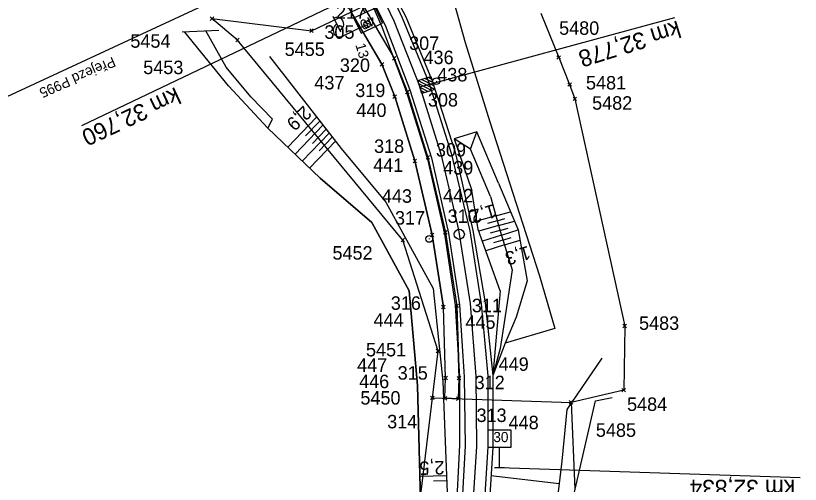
# Model space of a CAD drawing. Extents: x -804166 to -803706, y -1151030 to -1150147.
# Drawn here: x -803925.7 to -803809.4, y -1150585.6 to -1150516 of the extents above; entities that cross this region are included whole.
import ezdxf

# ---------------------------------------------------------------- set-up
doc = ezdxf.new("R2010")
doc.units = 0
for name, color, linetype in [('0381KM032-037P - Vrstva 1', 7, 'Continuous'), ('0381KM032-037P - Vrstva 16', 7, 'Continuous'), ('0381KM032-037P - Vrstva 17', 7, 'Continuous'), ('0381KM032-037P - Vrstva 25', 7, 'Continuous'), ('0381KM032-037P - Vrstva 27', 7, 'Continuous'), ('0381KM032-037P - Vrstva 3', 7, 'Continuous'), ('0381KM032-037P - Vrstva 4', 7, 'Continuous'), ('0381KM032-037P - Vrstva 48', 7, 'Continuous'), ('0381KM032-037P - Vrstva 49', 7, 'Continuous'), ('0381KM032-037P - Vrstva 5', 7, 'Continuous'), ('0381KM032-037P - Vrstva 50', 7, 'Continuous'), ('0381KM032-037P - Vrstva 55', 7, 'Continuous'), ('0381KM032-037P - Vrstva 7', 7, 'Continuous'), ('DZ - DZ_číslo', 7, 'Continuous'), ('DZ_CD - CD', 7, 'Continuous'), ('DZ_CD - CD_krizek', 7, 'Continuous'), ('DZ_CD - CD_čísla', 7, 'Continuous'), ('szdc - hran DP', 7, 'Continuous'), ('szdc - szdc_cislo', 7, 'Continuous'), ('szdc - szdc_krizek', 7, 'Continuous'), ('VB - VB', 7, 'Continuous'), ('VB - VB_cislo', 7, 'Continuous'), ('VB - VB_krizek', 7, 'Continuous')]:
    doc.layers.add(name, color=color, linetype=linetype)

msp = doc.modelspace()

# ---------------------------------------------------------------- linework, layer by layer
at = {"layer": '0381KM032-037P - Vrstva 1'}
for points in [[(-803874.07, -1150507.54), (-803869.67, -1150516.77), (-803865.8, -1150526.59), (-803862.65, -1150536.71)], [(-803862.65, -1150536.71), (-803860.06, -1150547.81), (-803858.36, -1150558.72), (-803857.51, -1150569.55), (-803857.43, -1150579.98), (-803858.1, -1150590.73), (-803859.58, -1150601.69), (-803861.73, -1150611.95), (-803864.69, -1150622.33), (-803868.31, -1150632.26), (-803873.12, -1150643.01), (-803878.78, -1150653.32), (-803884.46, -1150662.04), (-803890.68, -1150670.29), (-803894.47, -1150674.77)]]:
    msp.add_lwpolyline(points, dxfattribs=at)
at = {"layer": '0381KM032-037P - Vrstva 16'}
msp.add_line((-803901.04, -1150518.4), (-803895.63, -1150518.18), dxfattribs=at)
msp.add_lwpolyline([(-803888.33, -1150532.7), (-803887.64, -1150531.39), (-803890.89, -1150528.08), (-803894.53, -1150523.66), (-803897.53, -1150518.27)], dxfattribs=at)
at = {"layer": '0381KM032-037P - Vrstva 17'}
msp.add_lwpolyline([(-803867.91, -1150651.01), (-803864.19, -1150640.97), (-803863.34, -1150639.85), (-803860.11, -1150635.35), (-803857.38, -1150629.01), (-803845.63, -1150598.77), (-803839.77, -1150573.18), (-803837.29, -1150572.72)], dxfattribs=at)
at = {"layer": '0381KM032-037P - Vrstva 25'}
for p, q in [((-803877.52, -1150518.44), (-803878.68, -1150516.11)), ((-803873.28, -1150517.66), (-803874.12, -1150517.38)), ((-803873.13, -1150517.32), (-803874.04, -1150517.01)), ((-803874.08, -1150517.52), (-803877.21, -1150519.07))]:
    msp.add_line(p, q, dxfattribs=at)
msp.add_circle((-803873.63, -1150517.29), 0.5, dxfattribs=at)
msp.add_circle((-803873.63, -1150517.29), 0.5, dxfattribs=at)
for centre, start, end in [((-803878.09, -1150517.27), 295.6449, 117.05), ((-803877.66, -1150518.17), 116.3474, 296.3474)]:
    msp.add_arc(centre, 1, start, end, dxfattribs=at)
at = {"layer": '0381KM032-037P - Vrstva 27'}
msp.add_line((-803863.38, -1150525.68), (-803863.35, -1150525.78), dxfattribs=at)
msp.add_circle((-803863.37, -1150525.73), 0.5, dxfattribs=at)
at = {"layer": '0381KM032-037P - Vrstva 3'}
for p, q in [((-803865.8, -1150526.59), (-803827.99, -1150516.3)), ((-803863.75, -1150526.45), (-803865.59, -1150525.48)), ((-803863.91, -1150525.94), (-803865.09, -1150525.32)), ((-803864.07, -1150525.43), (-803864.58, -1150525.17)), ((-803863.59, -1150526.95), (-803866.1, -1150525.64)), ((-803864.1, -1150527.11), (-803865.94, -1150526.15)), ((-803864.61, -1150527.27), (-803865.78, -1150526.65)), ((-803865.11, -1150527.43), (-803865.62, -1150527.16))]:
    msp.add_line(p, q, dxfattribs=at)
msp.add_lwpolyline([(-803865.5, -1150527.55), (-803866.1, -1150525.64), (-803864.19, -1150525.04), (-803863.59, -1150526.95)], close=True, dxfattribs=at)
at = {"layer": '0381KM032-037P - Vrstva 4'}
msp.add_line((-803875.88, -1150504.25), (-803939.78, -1150533.94), dxfattribs=at)
for points in [[(-803872.78, -1150506.88), (-803867.87, -1150516.17), (-803864, -1150525.68), (-803860.6, -1150536.29), (-803857.96, -1150547.89), (-803856.11, -1150558.65), (-803855.01, -1150569.42), (-803855.01, -1150580.14), (-803855.68, -1150591.14), (-803857.11, -1150602.1)], [(-803872.78, -1150506.88), (-803868.42, -1150516.34), (-803864.49, -1150525.92), (-803861.19, -1150536.4), (-803858.42, -1150547.95), (-803856.72, -1150558.77), (-803855.71, -1150569.46), (-803855.71, -1150580.04), (-803856.44, -1150591.04), (-803858.02, -1150602.01)], [(-803875.39, -1150508.51), (-803870.94, -1150517.43), (-803867.28, -1150527.02), (-803864.07, -1150537.14), (-803861.55, -1150548.3), (-803859.95, -1150558.94), (-803859.25, -1150569.65), (-803859.08, -1150579.87)], [(-803875.39, -1150508.51), (-803871.45, -1150517.68), (-803867.83, -1150527.24), (-803864.66, -1150537.29), (-803862.15, -1150548.38), (-803860.59, -1150559), (-803859.92, -1150569.63), (-803859.95, -1150579.8), (-803860.5, -1150590.58), (-803862.04, -1150601.17)], [(-803859.08, -1150579.87), (-803859.7, -1150590.69), (-803861.11, -1150601.39)]]:
    msp.add_lwpolyline(points, dxfattribs=at)
at = {"layer": '0381KM032-037P - Vrstva 48'}
for p, q in [((-803881.12, -1150531.07), (-803885.4, -1150535.52)), ((-803880.19, -1150532.26), (-803884.32, -1150536.56)), ((-803880.65, -1150531.67), (-803882.76, -1150533.85)), ((-803879.26, -1150533.46), (-803883.24, -1150537.6)), ((-803879.72, -1150532.86), (-803881.75, -1150534.97)), ((-803878.32, -1150534.65), (-803882.16, -1150538.64)), ((-803878.79, -1150534.06), (-803880.74, -1150536.09)), ((-803854.54, -1150545.73), (-803852.36, -1150545.13)), ((-803854.54, -1150545.73), (-803857.36, -1150546.5)), ((-803854.34, -1150546.45), (-803855.79, -1150546.85)), ((-803854.34, -1150546.45), (-803853.2, -1150546.14)), ((-803854.14, -1150547.18), (-803851.77, -1150546.53)), ((-803854.14, -1150547.18), (-803857.07, -1150547.98)), ((-803853.95, -1150547.9), (-803852.71, -1150547.56)), ((-803853.73, -1150548.62), (-803856.53, -1150549.49)), ((-803853.95, -1150547.9), (-803855.38, -1150548.29)), ((-803853.73, -1150548.62), (-803851.22, -1150547.83)), ((-803853.5, -1150549.33), (-803854.89, -1150549.76)), ((-803853.5, -1150549.33), (-803852.29, -1150548.96)), ((-803853.28, -1150550.05), (-803850.96, -1150549.32)), ((-803853.28, -1150550.05), (-803856.02, -1150550.9)), ((-803861.84, -1150584.31), (-803865.81, -1150584.42)), ((-803845.17, -1150585.52), (-803855.27, -1150584.31)), ((-803861.81, -1150585.06), (-803863.8, -1150585.11))]:
    msp.add_line(p, q, dxfattribs=at)
at = {"layer": '0381KM032-037P - Vrstva 49'}
for p, q in [((-803858.31, -1150535.81), (-803857.36, -1150533.26)), ((-803853.88, -1150556.86), (-803855.01, -1150569.42)), ((-803853.88, -1150565.43), (-803855.01, -1150569.42))]:
    msp.add_line(p, q, dxfattribs=at)
for points in [[(-803866.91, -1150495.14), (-803866.85, -1150501.09), (-803862.34, -1150508.28), (-803859.07, -1150519.98)], [(-803859.07, -1150519.98), (-803855.45, -1150531.75), (-803848.06, -1150554.62), (-803845.79, -1150562.48), (-803853.14, -1150564.61), (-803855.01, -1150569.42)], [(-803888.13, -1150522.06), (-803877.5, -1150535.71), (-803870.85, -1150543.68), (-803863.85, -1150556.52), (-803862.4, -1150570.31), (-803861.64, -1150589.37), (-803863.02, -1150600.18)], [(-803888.33, -1150532.7), (-803880.59, -1150540.15), (-803872.91, -1150546.74), (-803867.41, -1150556.86), (-803866.18, -1150570.9), (-803865.67, -1150589.81), (-803867.32, -1150599.81), (-803870.94, -1150611.9)], [(-803854.16, -1150540.88), (-803857.36, -1150533.26), (-803860.71, -1150534.28), (-803858.11, -1150541.98)], [(-803855.32, -1150542.86), (-803858.31, -1150535.81), (-803860.71, -1150534.28)], [(-803854.16, -1150540.88), (-803851.22, -1150547.82), (-803849.9, -1150555.36)], [(-803853.88, -1150556.86), (-803857.15, -1150547.75), (-803858.11, -1150541.98)], [(-803855.32, -1150542.86), (-803853.92, -1150547.99), (-803852.13, -1150553.73)], [(-803852.13, -1150553.73), (-803853.33, -1150561.55), (-803853.88, -1150565.43)], [(-803849.9, -1150555.36), (-803851.52, -1150560.76), (-803853.14, -1150564.61)], [(-803838.83, -1150566.88), (-803844.04, -1150574.5), (-803844.76, -1150582.15), (-803846.56, -1150597.04), (-803847.17, -1150599.75), (-803857.38, -1150629.01)], [(-803855.01, -1150569.42), (-803855.01, -1150580.14), (-803855.68, -1150591.14), (-803857.11, -1150602.1), (-803859.61, -1150612.52), (-803862.49, -1150623.34), (-803866.1, -1150633.18), (-803870.87, -1150644.18), (-803876.81, -1150654.69), (-803882.51, -1150663.41)]]:
    msp.add_lwpolyline(points, dxfattribs=at)
at = {"layer": '0381KM032-037P - Vrstva 5'}
for p, q in [((-803875.27, -1150512.9), (-803915.96, -1150532.37)), ((-803854.75, -1150583.07), (-803853.25, -1150583.07)), ((-803854, -1150583.07), (-803809.4, -1150584.6))]:
    msp.add_line(p, q, dxfattribs=at)
for points in [[(-803875.27, -1150512.9), (-803873.99, -1150515.61), (-803875.58, -1150516.36), (-803874.51, -1150518.62), (-803871.34, -1150517.13), (-803872.41, -1150514.87), (-803873.99, -1150515.61)], [(-803854, -1150583.07), (-803854, -1150580.07), (-803852.25, -1150580.07), (-803852.25, -1150577.57), (-803855.75, -1150577.57), (-803855.75, -1150580.07), (-803854, -1150580.07)]]:
    msp.add_lwpolyline(points, dxfattribs=at)
at = {"layer": '0381KM032-037P - Vrstva 50'}
msp.add_lwpolyline([(-803870.94, -1150611.9), (-803867.32, -1150599.81), (-803865.67, -1150589.81), (-803866.18, -1150570.9), (-803867.41, -1150556.86), (-803872.91, -1150546.74), (-803880.59, -1150540.15), (-803888.33, -1150532.7), (-803894.19, -1150526.42), (-803900.65, -1150518.48)], dxfattribs=at)
at = {"layer": '0381KM032-037P - Vrstva 55'}
msp.add_line((-803863.95, -1150572.75), (-803843.4, -1150573.43), dxfattribs=at)
at = {"layer": '0381KM032-037P - Vrstva 7'}
msp.add_line((-803864.42, -1150549.11), (-803864.41, -1150549.21), dxfattribs=at)
for centre, radius in [((-803864.41, -1150549.16), 0.5), ((-803859.96, -1150548.47), 0.75)]:
    msp.add_circle(centre, radius, dxfattribs=at)
at = {"layer": 'DZ_CD - CD'}
for p, q in [((-803874.18, -1150514.59), (-803869.62, -1150522.34)), ((-803871.43, -1150523.22), (-803876, -1150515.45)), ((-803869.54, -1150528.03), (-803871.43, -1150523.22)), ((-803869.62, -1150522.34), (-803867.65, -1150527.36)), ((-803867.65, -1150527.36), (-803864.62, -1150537.05)), ((-803866.56, -1150537.58), (-803869.54, -1150528.03)), ((-803864.62, -1150537.05), (-803862.02, -1150548.19)), ((-803863.99, -1150548.57), (-803866.56, -1150537.58)), ((-803862.33, -1150559.27), (-803863.99, -1150548.57)), ((-803862.02, -1150548.19), (-803860.33, -1150559.09)), ((-803862, -1150569.82), (-803862.33, -1150559.27)), ((-803860.33, -1150559.09), (-803860, -1150569.82)), ((-803862.1, -1150572.81), (-803862, -1150569.82)), ((-803860, -1150569.82), (-803860.1, -1150572.88)), ((-803860.1, -1150572.88), (-803862.1, -1150572.81))]:
    msp.add_line(p, q, dxfattribs=at)
at = {"layer": 'DZ_CD - CD_krizek'}
for p, q in [((-803869.36, -1150522.61), (-803869.89, -1150522.08)), ((-803869.89, -1150522.61), (-803869.36, -1150522.08)), ((-803871.16, -1150523.49), (-803871.69, -1150522.96)), ((-803871.69, -1150523.49), (-803871.16, -1150522.96)), ((-803869.27, -1150528.29), (-803869.8, -1150527.76)), ((-803869.8, -1150528.29), (-803869.27, -1150527.76)), ((-803867.38, -1150527.62), (-803867.92, -1150527.09)), ((-803867.92, -1150527.62), (-803867.38, -1150527.09)), ((-803864.36, -1150537.32), (-803864.89, -1150536.79)), ((-803864.89, -1150537.32), (-803864.36, -1150536.79)), ((-803866.29, -1150537.84), (-803866.82, -1150537.31)), ((-803866.82, -1150537.84), (-803866.29, -1150537.31)), ((-803863.72, -1150548.84), (-803864.25, -1150548.31)), ((-803864.25, -1150548.84), (-803863.72, -1150548.31)), ((-803861.76, -1150548.46), (-803862.29, -1150547.93)), ((-803862.29, -1150548.46), (-803861.76, -1150547.93)), ((-803862.06, -1150559.54), (-803862.59, -1150559.01)), ((-803862.59, -1150559.54), (-803862.06, -1150559.01)), ((-803860.07, -1150559.35), (-803860.6, -1150558.82)), ((-803860.6, -1150559.35), (-803860.07, -1150558.82)), ((-803861.73, -1150570.08), (-803862.27, -1150569.55)), ((-803862.27, -1150570.08), (-803861.73, -1150569.55)), ((-803859.73, -1150570.09), (-803860.27, -1150569.56)), ((-803860.27, -1150570.09), (-803859.73, -1150569.56)), ((-803861.83, -1150573.08), (-803862.36, -1150572.55)), ((-803862.36, -1150573.08), (-803861.83, -1150572.55)), ((-803859.83, -1150573.14), (-803860.36, -1150572.61)), ((-803860.36, -1150573.14), (-803859.83, -1150572.61))]:
    msp.add_line(p, q, dxfattribs=at)
at = {"layer": 'szdc - hran DP'}
for p, q in [((-803881.88, -1150518.24), (-803874.06, -1150514.53)), ((-803847.85, -1150515.64), (-803845.22, -1150522.21)), ((-803892.84, -1150519.63), (-803896.64, -1150516.44)), ((-803896.64, -1150516.44), (-803881.88, -1150518.24)), ((-803868.33, -1150549.32), (-803892.84, -1150519.63)), ((-803845.22, -1150522.21), (-803843.61, -1150526.23)), ((-803843.61, -1150526.23), (-803842.82, -1150528.36)), ((-803842.82, -1150528.36), (-803835.43, -1150562.1)), ((-803863.11, -1150565.8), (-803868.33, -1150549.32)), ((-803835.43, -1150562.1), (-803835.59, -1150571.61)), ((-803863.95, -1150572.75), (-803863.11, -1150565.8)), ((-803835.59, -1150571.61), (-803843.4, -1150573.43)), ((-803868.49, -1150610.44), (-803863.95, -1150572.75)), ((-803843.4, -1150573.43), (-803842.82, -1150586.3))]:
    msp.add_line(p, q, dxfattribs=at)
at = {"layer": 'szdc - szdc_krizek'}
for p, q in [((-803896.38, -1150516.71), (-803896.91, -1150516.18)), ((-803896.91, -1150516.71), (-803896.38, -1150516.18)), ((-803881.61, -1150518.51), (-803882.15, -1150517.98)), ((-803882.15, -1150518.51), (-803881.61, -1150517.98)), ((-803892.58, -1150519.9), (-803893.11, -1150519.36)), ((-803893.11, -1150519.9), (-803892.58, -1150519.36)), ((-803844.96, -1150522.48), (-803845.49, -1150521.95)), ((-803845.49, -1150522.48), (-803844.96, -1150521.95)), ((-803843.34, -1150526.5), (-803843.88, -1150525.97)), ((-803843.88, -1150526.5), (-803843.34, -1150525.97)), ((-803842.56, -1150528.62), (-803843.09, -1150528.09)), ((-803843.09, -1150528.62), (-803842.56, -1150528.09)), ((-803868.07, -1150549.58), (-803868.6, -1150549.05)), ((-803868.6, -1150549.58), (-803868.07, -1150549.05)), ((-803835.17, -1150562.36), (-803835.7, -1150561.83)), ((-803835.7, -1150562.36), (-803835.17, -1150561.83)), ((-803862.84, -1150566.06), (-803863.38, -1150565.53)), ((-803863.38, -1150566.06), (-803862.84, -1150565.53)), ((-803835.33, -1150571.88), (-803835.86, -1150571.34)), ((-803835.86, -1150571.88), (-803835.33, -1150571.34)), ((-803863.69, -1150573.02), (-803864.22, -1150572.49)), ((-803864.22, -1150573.02), (-803863.69, -1150572.49)), ((-803843.14, -1150573.7), (-803843.67, -1150573.17)), ((-803843.67, -1150573.7), (-803843.14, -1150573.17))]:
    msp.add_line(p, q, dxfattribs=at)
at = {"layer": 'VB - VB'}
for p, q in [((-803883.67, -1150498.44), (-803869.62, -1150522.34)), ((-803885.33, -1150499.57), (-803871.43, -1150523.22)), ((-803871.43, -1150523.22), (-803869.54, -1150528.03)), ((-803869.62, -1150522.34), (-803867.65, -1150527.36)), ((-803867.65, -1150527.36), (-803864.62, -1150537.05)), ((-803869.54, -1150528.03), (-803866.56, -1150537.58)), ((-803864.62, -1150537.05), (-803862.02, -1150548.19)), ((-803866.56, -1150537.58), (-803863.99, -1150548.57)), ((-803863.99, -1150548.57), (-803862.33, -1150559.27)), ((-803862.02, -1150548.19), (-803860.33, -1150559.09))]:
    msp.add_line(p, q, dxfattribs=at)
for points in [[(-803862.1, -1150572.81), (-803862, -1150569.82), (-803862.33, -1150559.27)], [(-803862.1, -1150572.81), (-803860.1, -1150572.88), (-803860, -1150569.82), (-803860.33, -1150559.09)]]:
    msp.add_lwpolyline(points, dxfattribs=at)
at = {"layer": 'VB - VB_krizek'}
for p, q in [((-803869.36, -1150522.61), (-803869.89, -1150522.08)), ((-803869.89, -1150522.61), (-803869.36, -1150522.08)), ((-803871.16, -1150523.49), (-803871.69, -1150522.96)), ((-803871.69, -1150523.49), (-803871.16, -1150522.96)), ((-803869.27, -1150528.29), (-803869.8, -1150527.76)), ((-803869.8, -1150528.29), (-803869.27, -1150527.76)), ((-803867.38, -1150527.62), (-803867.92, -1150527.09)), ((-803867.92, -1150527.62), (-803867.38, -1150527.09)), ((-803864.36, -1150537.32), (-803864.89, -1150536.79)), ((-803864.89, -1150537.32), (-803864.36, -1150536.79)), ((-803866.29, -1150537.84), (-803866.82, -1150537.31)), ((-803866.82, -1150537.84), (-803866.29, -1150537.31)), ((-803863.72, -1150548.84), (-803864.25, -1150548.31)), ((-803864.25, -1150548.84), (-803863.72, -1150548.31)), ((-803861.76, -1150548.46), (-803862.29, -1150547.93)), ((-803862.29, -1150548.46), (-803861.76, -1150547.93)), ((-803862.06, -1150559.54), (-803862.59, -1150559.01)), ((-803862.59, -1150559.54), (-803862.06, -1150559.01)), ((-803860.07, -1150559.35), (-803860.6, -1150558.82)), ((-803860.6, -1150559.35), (-803860.07, -1150558.82)), ((-803861.73, -1150570.08), (-803862.27, -1150569.55)), ((-803862.27, -1150570.08), (-803861.73, -1150569.55)), ((-803859.73, -1150570.09), (-803860.27, -1150569.56)), ((-803860.27, -1150570.09), (-803859.73, -1150569.56)), ((-803861.83, -1150573.08), (-803862.36, -1150572.55)), ((-803862.36, -1150573.08), (-803861.83, -1150572.55)), ((-803859.83, -1150573.14), (-803860.36, -1150572.61)), ((-803860.36, -1150573.14), (-803859.83, -1150572.61))]:
    msp.add_line(p, q, dxfattribs=at)

# ---------------------------------------------------------------- texts
at = {"layer": '0381KM032-037P - Vrstva 25'}
msp.add_text('13', height=1.5, rotation=286.3474, dxfattribs=at).set_placement((-803875.38, -1150520.34))
at = {"layer": '0381KM032-037P - Vrstva 3'}
msp.add_text('km 32,778', height=2.5, rotation=197.3269, dxfattribs=at).set_placement((-803827.6, -1150516.69))
at = {"layer": '0381KM032-037P - Vrstva 4'}
msp.add_text('Přejezd P995', height=1.5, rotation=203.5952, dxfattribs=at).set_placement((-803911.35, -1150522.08))
at = {"layer": '0381KM032-037P - Vrstva 48'}
for s, rotation, p in [('2,9', 222.9189, (-803883.02, -1150529.26)), ('1,2', 196.3519, (-803854.89, -1150543.96)), ('1,3', 196.3801, (-803849.77, -1150550.15)), ('2,5', 181.5324, (-803862.19, -1150582.11))]:
    msp.add_text(s, height=2, rotation=rotation, dxfattribs=at).set_placement(p)
at = {"layer": '0381KM032-037P - Vrstva 5'}
for s, height, rotation, p in [('40', 1.5, 205.1322, (-803872.85, -1150515.9)), ('km 32,760', 2.5, 205.1322, (-803902.06, -1150526.56)), ('km 32,834', 2.5, 180, (-803810.18, -1150584.92))]:
    msp.add_text(s, height=height, rotation=rotation, dxfattribs=at).set_placement(p)
msp.add_text('30', height=1.5, dxfattribs=at).set_placement((-803854.91, -1150579.32))
at = {"layer": 'DZ - DZ_číslo'}
msp.add_text('217', height=2, dxfattribs=at).set_placement((-803878.24, -1150516.45))
at = {"layer": 'DZ_CD - CD_čísla'}
for s, p in [('305', (-803879.97, -1150519.44)), ('307', (-803867.4, -1150521.1)), ('320', (-803877.67, -1150524.36)), ('319', (-803875.39, -1150528.09)), ('308', (-803864.62, -1150529.5)), ('318', (-803872.6, -1150536.39)), ('309', (-803863.43, -1150536.93)), ('317', (-803869.5, -1150547.03)), ('310', (-803861.69, -1150546.77)), ('316', (-803870.12, -1150559.68)), ('311', (-803858.1, -1150560.04)), ('315', (-803869.1, -1150570.05)), ('312', (-803857.69, -1150571.47)), ('313', (-803857.41, -1150576.34)), ('314', (-803870.66, -1150577.28))]:
    msp.add_text(s, height=2, dxfattribs=at).set_placement(p)
at = {"layer": 'szdc - szdc_cislo'}
for s, p in [('5480', (-803845.16, -1150518.85)), ('5454', (-803908.74, -1150520.77)), ('5455', (-803885.86, -1150521.99)), ('5453', (-803906.83, -1150524.69)), ('5481', (-803841.18, -1150526.97)), ('5482', (-803840.27, -1150529.97)), ('5452', (-803878.77, -1150552.23)), ('5483', (-803833.31, -1150562.66)), ('5451', (-803873.8, -1150566.6)), ('5450', (-803874.63, -1150573.75)), ('5484', (-803835.09, -1150574.7)), ('5485', (-803839.71, -1150578.54))]:
    msp.add_text(s, height=2, dxfattribs=at).set_placement(p)
at = {"layer": 'VB - VB_cislo'}
for s, p in [('436', (-803865.27, -1150523.2)), ('438', (-803863.23, -1150525.77)), ('437', (-803881.46, -1150526.96)), ('440', (-803875.22, -1150531.04)), ('441', (-803872.73, -1150539.2)), ('439', (-803862.35, -1150539.58)), ('443', (-803871.44, -1150543.79)), ('442', (-803862.37, -1150543.73)), ('444', (-803872.67, -1150562.18)), ('445', (-803859.06, -1150562.5)), ('447', (-803875.12, -1150568.89)), ('449', (-803854.13, -1150568.74)), ('446', (-803874.82, -1150571.31)), ('448', (-803852.65, -1150577.41))]:
    msp.add_text(s, height=2, dxfattribs=at).set_placement(p)

doc.saveas('drawing.dxf')
